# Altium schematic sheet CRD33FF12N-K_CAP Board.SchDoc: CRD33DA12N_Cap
size 431 x 279 mm; Date: 03.07.2025; Revision: 1; SheetNumber: 1; SheetTotal: 1; SheetSize: B
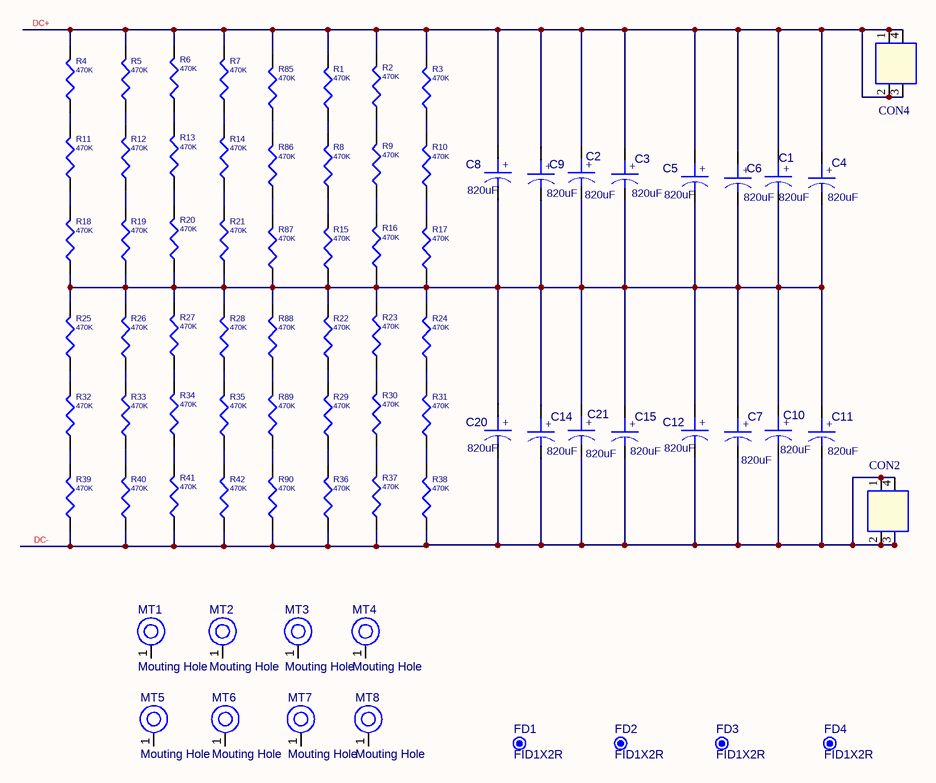
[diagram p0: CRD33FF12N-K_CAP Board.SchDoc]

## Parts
C1  820uF  [CAP2_2100_6000_3000]
C2  820uF  [CAP2_2100_6000_3000]
C3  820uF  [CAP2_2100_6000_3000]
C4  820uF  [CAP2_2100_6000_3000]
C5  820uF  [CAP2_2100_6000_3000]
C6  820uF  [CAP2_2100_6000_3000]
C7  820uF  [CAP2_2100_6000_3000]
C8  820uF  [CAP2_2100_6000_3000]
C9  820uF  [CAP2_2100_6000_3000]
C10  820uF  [CAP2_2100_6000_3000]
C11  820uF  [CAP2_2100_6000_3000]
C12  820uF  [CAP2_2100_6000_3000]
C14  820uF  [CAP2_2100_6000_3000]
C15  820uF  [CAP2_2100_6000_3000]
C20  820uF  [CAP2_2100_6000_3000]
C21  820uF  [CAP2_2100_6000_3000]
CON2  Connecter  [thread4_9p9x5_1110x920]  (value not drawn)
CON4  Connecter  [thread4_9p9x5_1110x920]  (value not drawn)
FD1  FID1X2R  [FID1X2R]  (no BOM)
FD2  FID1X2R  [FID1X2R]  (no BOM)
FD3  FID1X2R  [FID1X2R]  (no BOM)
FD4  FID1X2R  [FID1X2R]  (no BOM)
MT1  Mouting Hole  [MTG330N]  (no BOM)
MT2  Mouting Hole  [MTG330N]  (no BOM)
MT3  Mouting Hole  [MTG330N]  (no BOM)
MT4  Mouting Hole  [MTG330N]  (no BOM)
MT5  Mouting Hole  [MTG330N]  (no BOM)
MT6  Mouting Hole  [MTG330N]  (no BOM)
MT7  Mouting Hole  [MTG330N]  (no BOM)
MT8  Mouting Hole  [MTG330N]  (no BOM)
R1  470K  [1206]
R2  470K  [1206]
R3  470K  [1206]
R4  470K  [1206]
R5  470K  [1206]
R6  470K  [1206]
R7  470K  [1206]
R8  470K  [1206]
R9  470K  [1206]
R10  470K  [1206]
R11  470K  [1206]
R12  470K  [1206]
R13  470K  [1206]
R14  470K  [1206]
R15  470K  [1206]
R16  470K  [1206]
R17  470K  [1206]
R18  470K  [1206]
R19  470K  [1206]
R20  470K  [1206]
R21  470K  [1206]
R22  470K  [1206]
R23  470K  [1206]
R24  470K  [1206]
R25  470K  [1206]
R26  470K  [1206]
R27  470K  [1206]
R28  470K  [1206]
R29  470K  [1206]
R30  470K  [1206]
R31  470K  [1206]
R32  470K  [1206]
R33  470K  [1206]
R34  470K  [1206]
R35  470K  [1206]
R36  470K  [1206]
R37  470K  [1206]
R38  470K  [1206]
R39  470K  [1206]
R40  470K  [1206]
R41  470K  [1206]
R42  470K  [1206]
R85  470K  [1206]
R86  470K  [1206]
R87  470K  [1206]
R88  470K  [1206]
R89  470K  [1206]
R90  470K  [1206]

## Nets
DC+: C1.1 C2.1 C3.1 C4.1 C5.1 C6.1 C8.1 C9.1 CON4.1 CON4.2 CON4.3 CON4.4 R1.2 R2.2 R3.2 R4.2 R5.2 R6.2 R7.2 R85.2
DC-: C7.2 C10.2 C11.2 C12.2 C14.2 C15.2 C20.2 C21.2 CON2.1 CON2.2 CON2.3 CON2.4 R36.1 R37.1 R38.1 R39.1 R40.1 R41.1 R42.1 R90.1
NetC1_2: C1.2 C2.2 C3.2 C4.2 C5.2 C6.2 C7.1 C8.2 C9.2 C10.1 C11.1 C12.1 C14.1 C15.1 C20.1 C21.1 R15.1 R16.1 R17.1 R18.1 R19.1 R20.1 R21.1 R22.2 R23.2 R24.2 R25.2 R26.2 R27.2 R28.2 R87.1 R88.2
NetR1_1: R1.1 R8.2
NetR2_1: R2.1 R9.2
NetR3_1: R3.1 R10.2
NetR4_1: R4.1 R11.2
NetR5_1: R5.1 R12.2
NetR6_1: R6.1 R13.2
NetR7_1: R7.1 R14.2
NetR8_1: R8.1 R15.2
NetR9_1: R9.1 R16.2
NetR10_1: R10.1 R17.2
NetR11_1: R11.1 R18.2
NetR12_1: R12.1 R19.2
NetR13_1: R13.1 R20.2
NetR14_1: R14.1 R21.2
NetR22_1: R22.1 R29.2
NetR23_1: R23.1 R30.2
NetR24_1: R24.1 R31.2
NetR25_1: R25.1 R32.2
NetR26_1: R26.1 R33.2
NetR27_1: R27.1 R34.2
NetR28_1: R28.1 R35.2
NetR29_1: R29.1 R36.2
NetR30_1: R30.1 R37.2
NetR31_1: R31.1 R38.2
NetR32_1: R32.1 R39.2
NetR33_1: R33.1 R40.2
NetR34_1: R34.1 R41.2
NetR35_1: R35.1 R42.2
NetR85_1: R85.1 R86.2
NetR86_1: R86.1 R87.2
NetR88_1: R88.1 R89.2
NetR89_1: R89.1 R90.2

Not connected (* = marked no-connect by the designer): MT1 1(H1); MT2 1(H1); MT3 1(H1); MT4 1(H1); MT5 1(H1); MT6 1(H1); MT7 1(H1); MT8 1(H1)

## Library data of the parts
C1-C12 C14 C15 C20 C21 = 820u: CAP ALUM 820UF 20% 450V RADIAL; PCB Footprint: C0805
FD1-FD4 = CMP-00028-00005-1: Fiducial - Round 1x2mm
MT1-MT8 = MTG330N: PCB Mounting Hole
R1-R42 R85-R90 = RESISTOR_Dup1: RES SMD 470K OHM 1% 1/10W 1206; Manufacturer: Yageo; PCB Footprint: R1206; PN: AC1206FR-07470KL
